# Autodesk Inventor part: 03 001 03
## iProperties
Shininess: 64.0
Length Units: 11269
Angle Units: 11279
Time Units: 11290
Mass Units: 11283
Length Display Precision: 3
Angle Display Precision: 2
Compacted: True
Part Number: 03 001 03
Document SubType Name: Modeling
Created: 2003-12
Material: Standard
Designer: HAH
Manufacturer: Standard
Standards Organization: Custom
Description: Wand B
Density: 0.0
Volumn: 0.0
Area: 0.0
PropertySet Name: Model Information
Control State: 0
Master: False
Checked Out: False
Author: HAH
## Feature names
1. Extrusion1
